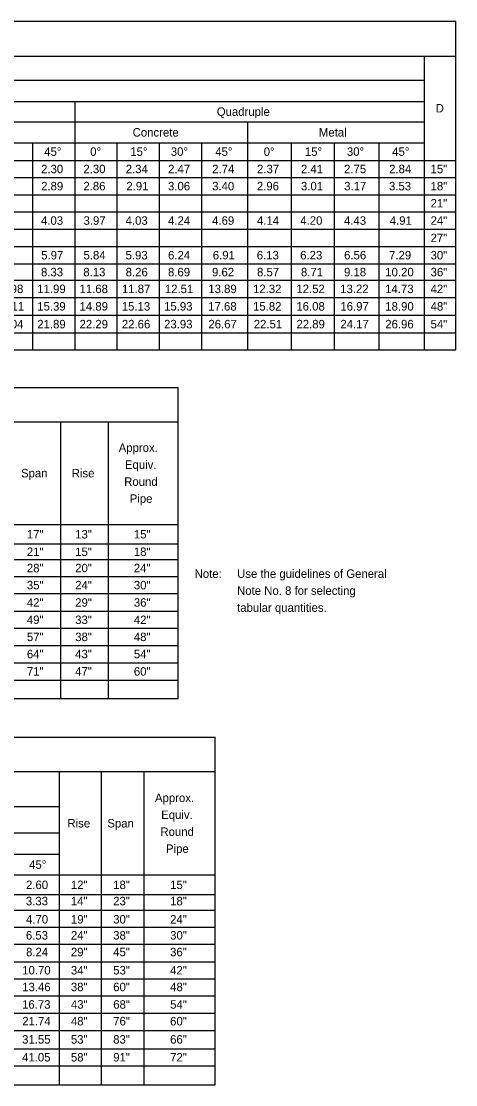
# Model space of a CAD drawing. Extents: x 10029 to 10796, y 10063 to 10519.
# Drawn here: x 10616.8 to 10795.9, y 10063.2 to 10502 of the extents above; entities that cross this region are included whole.
import ezdxf

# ---------------------------------------------------------------- set-up
doc = ezdxf.new("R2010")
doc.units = 0
doc.layers.add('Default', color=7, linetype='Continuous')
doc.layers.add('TextStructures', color=7, linetype='Continuous')

msp = doc.modelspace()

# ---------------------------------------------------------------- linework, layer by layer
at = {"layer": 'Default'}
for p, q in [((10028.97, 10502.01), (10795.89, 10502.01)), ((10795.89, 10366.47), (10795.89, 10502.01)), ((10028.97, 10487.65), (10795.89, 10487.65)), ((10783.03, 10366.47), (10783.03, 10487.65)), ((10326.86, 10477.72), (10783.03, 10477.72)), ((10326.86, 10468.97), (10783.03, 10468.97)), ((10638.95, 10366.47), (10638.95, 10468.97)), ((10042.36, 10460.49), (10783.03, 10460.49)), ((10710.2, 10366.47), (10710.2, 10460.49)), ((10244.78, 10451.88), (10783.03, 10451.88)), ((10621.51, 10366.47), (10621.51, 10451.88)), ((10656.39, 10366.47), (10656.39, 10451.88)), ((10673.82, 10366.47), (10673.82, 10451.88)), ((10691.26, 10366.47), (10691.26, 10451.88)), ((10728.19, 10366.47), (10728.19, 10451.88)), ((10745.95, 10366.47), (10745.95, 10451.88)), ((10764.33, 10366.47), (10764.33, 10451.88)), ((10795.89, 10366.47), (10795.89, 10451.88)), ((10028.97, 10444.58), (10795.89, 10444.58)), ((10028.97, 10437.55), (10795.89, 10437.55)), ((10028.97, 10430.43), (10795.89, 10430.43)), ((10028.97, 10423.41), (10795.89, 10423.41)), ((10028.97, 10416.18), (10795.89, 10416.18)), ((10028.97, 10409.08), (10795.89, 10409.08)), ((10028.97, 10401.92), (10795.89, 10401.92)), ((10028.97, 10395.12), (10795.89, 10395.12)), ((10028.97, 10388.08), (10795.89, 10388.08)), ((10028.97, 10380.7), (10795.89, 10380.7)), ((10028.97, 10373.4), (10795.89, 10373.4)), ((10028.97, 10366.47), (10795.89, 10366.47)), ((10039.72, 10350.86), (10681.45, 10350.86)), ((10681.45, 10222.58), (10681.45, 10350.86)), ((10039.72, 10336.74), (10681.45, 10336.74)), ((10633.08, 10222.58), (10633.08, 10336.74)), ((10652.82, 10222.58), (10652.82, 10336.74)), ((10039.72, 10294.39), (10681.45, 10294.39)), ((10039.72, 10286.34), (10681.45, 10286.34)), ((10039.72, 10279.92), (10681.45, 10279.92)), ((10039.72, 10272.9), (10681.45, 10272.9)), ((10039.72, 10265.84), (10681.45, 10265.84)), ((10039.72, 10258.56), (10681.45, 10258.56)), ((10039.72, 10251.55), (10681.45, 10251.55)), ((10039.72, 10244.47), (10681.45, 10244.47)), ((10039.72, 10237.36), (10681.45, 10237.36)), ((10039.72, 10230.15), (10681.45, 10230.15)), ((10039.72, 10222.58), (10681.45, 10222.58)), ((10040.76, 10206.56), (10696.75, 10206.56)), ((10696.75, 10063.22), (10696.75, 10206.56)), ((10040.76, 10192.44), (10696.75, 10192.44)), ((10632.55, 10063.22), (10632.55, 10192.44)), ((10649.82, 10063.22), (10649.82, 10192.44)), ((10667.43, 10063.22), (10667.43, 10192.44)), ((10386.23, 10178.05), (10632.55, 10178.05)), ((10084.96, 10167.22), (10632.55, 10167.22)), ((10303.39, 10158.32), (10632.55, 10158.32)), ((10040.76, 10149.78), (10696.75, 10149.78)), ((10040.76, 10141.72), (10696.75, 10141.72)), ((10040.76, 10135.31), (10696.75, 10135.31)), ((10040.76, 10128.29), (10696.75, 10128.29)), ((10040.76, 10121.22), (10696.75, 10121.22)), ((10040.76, 10113.95), (10696.75, 10113.95)), ((10040.76, 10106.93), (10696.75, 10106.93)), ((10040.76, 10099.86), (10696.75, 10099.86)), ((10040.76, 10092.75), (10696.75, 10092.75)), ((10040.76, 10085.54), (10696.75, 10085.54)), ((10040.76, 10077.97), (10696.75, 10077.97)), ((10040.76, 10071.08), (10696.75, 10071.08)), ((10040.76, 10063.22), (10696.75, 10063.22))]:
    msp.add_line(p, q, dxfattribs=at)

# ---------------------------------------------------------------- texts
at = {"layer": 'TextStructures'}
for s, p in [('Quadruple', (10697.4, 10462.98)), ('D', (10787.63, 10464.37)), ('Concrete', (10662.7, 10454.43)), ('Metal', (10739.48, 10454.43)), ('45°', (10626.25, 10446.48)), ('0°', (10645.21, 10446.48)), ('15°', (10661.75, 10446.48)), ('30°', (10678.43, 10446.48)), ('45°', (10696.76, 10446.48)), ('0°', (10716.74, 10446.48)), ('15°', (10733.72, 10446.48)), ('30°', (10751.03, 10446.48)), ('45°', (10769.71, 10446.48)), ('20.04', (10605.99, 10375.3)), ('21.89', (10623.39, 10375.3)), ('22.51', (10712.64, 10375.3)), ('22.89', (10730.24, 10375.3)), ('24.17', (10748.35, 10375.3)), ('26.96', (10766.85, 10375.3)), ('Approx.', (10656.96, 10324.32)), ('Equiv.', (10659.53, 10317.32)), ('Span', (10616.7, 10313.82)), ('Rise', (10637.61, 10313.82)), ('Round', (10659.22, 10310.32)), ('Pipe', (10661.51, 10303.32)), ('Approx.', (10671.91, 10179.86)), ('Equiv.', (10674.48, 10172.86)), ('Rise', (10635.84, 10169.36)), ('Span', (10652.29, 10169.36)), ('Round', (10674.17, 10165.86)), ('Pipe', (10676.45, 10158.86)), ('45°', (10620.03, 10152.3))]:
    msp.add_text(s, height=3.5, dxfattribs=at).set_placement(p)
for s, p in [('2.30', (10624.97, 10439.32)), ('2.30', (10642.41, 10439.32)), ('2.34', (10659.87, 10439.32)), ('2.47', (10677.32, 10439.32)), ('2.74', (10695.5, 10439.32)), ('2.37', (10713.98, 10439.32)), ('2.41', (10732.09, 10439.32)), ('2.75', (10749.85, 10439.32)), ('2.84', (10768.45, 10439.32)), ('15"', (10785.54, 10439.32)), ('2.89', (10624.97, 10432.24)), ('2.86', (10642.4, 10432.24)), ('2.91', (10660.12, 10432.24)), ('3.06', (10677.28, 10432.24)), ('3.40', (10695.48, 10432.24)), ('2.96', (10713.93, 10432.24)), ('3.01', (10732.09, 10432.24)), ('3.17', (10749.92, 10432.24)), ('3.53', (10768.38, 10432.24)), ('18"', (10785.54, 10432.24)), ('21"', (10785.54, 10425.17)), ('4.03', (10624.93, 10418.04)), ('3.97', (10642.45, 10418.04)), ('4.03', (10659.8, 10418.04)), ('4.24', (10677.31, 10418.04)), ('4.69', (10695.47, 10418.04)), ('4.14', (10713.97, 10418.04)), ('4.20', (10731.81, 10418.04)), ('4.43', (10749.84, 10418.04)), ('4.91', (10768.7, 10418.04)), ('24"', (10785.54, 10418.04)), ('27"', (10785.54, 10410.88)), ('5.97', (10625.01, 10403.75)), ('5.84', (10642.44, 10403.75)), ('5.93', (10659.8, 10403.75)), ('6.24', (10677.31, 10403.75)), ('6.91', (10695.75, 10403.75)), ('6.13', (10713.89, 10403.75)), ('6.23', (10731.77, 10403.75)), ('6.56', (10749.88, 10403.75)), ('7.29', (10768.42, 10403.75)), ('30"', (10785.54, 10403.75)), ('8.33', (10624.93, 10396.77)), ('8.13', (10642.36, 10396.77)), ('8.26', (10659.84, 10396.77)), ('8.69', (10677.28, 10396.77)), ('9.62', (10695.43, 10396.77)), ('8.57', (10713.98, 10396.77)), ('8.71', (10732.09, 10396.77)), ('9.18', (10749.85, 10396.77)), ('10.20', (10766.86, 10396.77)), ('36"', (10785.54, 10396.77)), ('10.98', (10605.93, 10389.85)), ('11.99', (10623.39, 10389.85)), ('11.68', (10640.81, 10389.85)), ('11.87', (10658.31, 10389.85)), ('12.51', (10675.99, 10389.85)), ('13.89', (10693.9, 10389.85)), ('12.32', (10712.33, 10389.85)), ('12.52', (10730.2, 10389.85)), ('13.22', (10748.27, 10389.85)), ('14.73', (10766.81, 10389.85)), ('42"', (10785.54, 10389.85)), ('14.11', (10606.23, 10382.64)), ('15.39', (10623.39, 10382.64)), ('14.89', (10640.83, 10382.64)), ('15.13', (10658.23, 10382.64)), ('15.93', (10675.67, 10382.64)), ('17.68', (10693.87, 10382.64)), ('15.82', (10712.33, 10382.64)), ('16.08', (10730.21, 10382.64)), ('16.97', (10748.35, 10382.64)), ('18.90', (10766.86, 10382.64)), ('48"', (10785.54, 10382.64)), ('22.29', (10640.83, 10375.3)), ('22.66', (10658.27, 10375.3)), ('23.93', (10675.67, 10375.3)), ('26.67', (10693.94, 10375.3)), ('54"', (10785.54, 10375.3)), ('17"', (10619.11, 10288.61)), ('13"', (10639.03, 10288.61)), ('15"', (10663.21, 10288.61)), ('21"', (10619.11, 10281.38)), ('15"', (10639.03, 10281.38)), ('18"', (10663.21, 10281.38)), ('28"', (10619.11, 10274.66)), ('20"', (10639.03, 10274.66)), ('24"', (10663.21, 10274.66)), ('Note:', (10688.26, 10272.34)), ('Use the guidelines of General ', (10705.76, 10272.34)), ('35"', (10619.11, 10267.62)), ('24"', (10639.03, 10267.62)), ('30"', (10663.21, 10267.62)), ('Note No. 8 for selecting ', (10705.76, 10265.34)), ('42"', (10619.11, 10260.45)), ('29"', (10639.03, 10260.45)), ('36"', (10663.21, 10260.45)), ('tabular quantities.', (10705.76, 10258.34)), ('49"', (10619.11, 10253.3)), ('33"', (10639.03, 10253.3)), ('42"', (10663.21, 10253.3)), ('57"', (10619.11, 10246.26)), ('38"', (10639.03, 10246.26)), ('48"', (10663.21, 10246.26)), ('64"', (10619.11, 10239.17)), ('43"', (10639.03, 10239.17)), ('54"', (10663.21, 10239.17)), ('71"', (10619.11, 10232.01)), ('47"', (10639.03, 10232.01)), ('60"', (10663.21, 10232.01)), ('2.60', (10618.75, 10143.95)), ('12"', (10637.26, 10143.95)), ('18"', (10654.7, 10143.95)), ('15"', (10678.16, 10143.95)), ('3.33', (10618.7, 10137.25)), ('14"', (10637.26, 10137.25)), ('23"', (10654.7, 10137.25)), ('18"', (10678.16, 10137.25)), ('4.70', (10618.75, 10129.73)), ('19"', (10637.26, 10129.73)), ('30"', (10654.7, 10129.73)), ('24"', (10678.16, 10129.73)), ('6.53', (10618.7, 10123.13)), ('24"', (10637.26, 10123.13)), ('38"', (10654.7, 10123.13)), ('30"', (10678.16, 10123.13)), ('8.24', (10618.77, 10116.23)), ('29"', (10637.26, 10116.23)), ('45"', (10654.7, 10116.23)), ('36"', (10678.16, 10116.23)), ('10.70', (10617.18, 10108.71)), ('34"', (10637.26, 10108.71)), ('53"', (10654.7, 10108.71)), ('42"', (10678.16, 10108.71)), ('13.46', (10617.17, 10101.81)), ('38"', (10637.26, 10101.81)), ('60"', (10654.7, 10101.81)), ('48"', (10678.16, 10101.81)), ('16.73', (10617.13, 10094.6)), ('43"', (10637.26, 10094.6)), ('68"', (10654.7, 10094.6)), ('54"', (10678.16, 10094.6)), ('21.74', (10617.2, 10087.7)), ('48"', (10637.26, 10087.7)), ('76"', (10654.7, 10087.7)), ('60"', (10678.16, 10087.7)), ('31.55', (10617.15, 10080.18)), ('53"', (10637.26, 10080.18)), ('83"', (10654.7, 10080.18)), ('66"', (10678.16, 10080.18)), ('41.05', (10617.15, 10072.81)), ('58"', (10637.26, 10072.81)), ('91"', (10654.7, 10072.81)), ('72"', (10678.16, 10072.81))]:
    msp.add_text(s, height=3.5, rotation=0, dxfattribs=at).set_placement(p)

doc.saveas('drawing.dxf')
